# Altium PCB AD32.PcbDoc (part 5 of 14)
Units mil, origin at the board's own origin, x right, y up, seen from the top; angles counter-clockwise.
Board outline 7007.87 x 4368.85 mil, 12 copper layers (Top Layer, Int1 (GND), Int2 (AVDD), Int3 (DVDD), Int4 (GND), Int5 (ST), Int6 (SB), Int8 (AGND), Int7 (AVCC), Int9 (VCCA), Int10 (GND), Bottom Layer), stack 60.136 mil thick; 1350 components, 880 nets, 4712 pads, 2835 vias.
Unrouted connection lines stored in the file: 19.
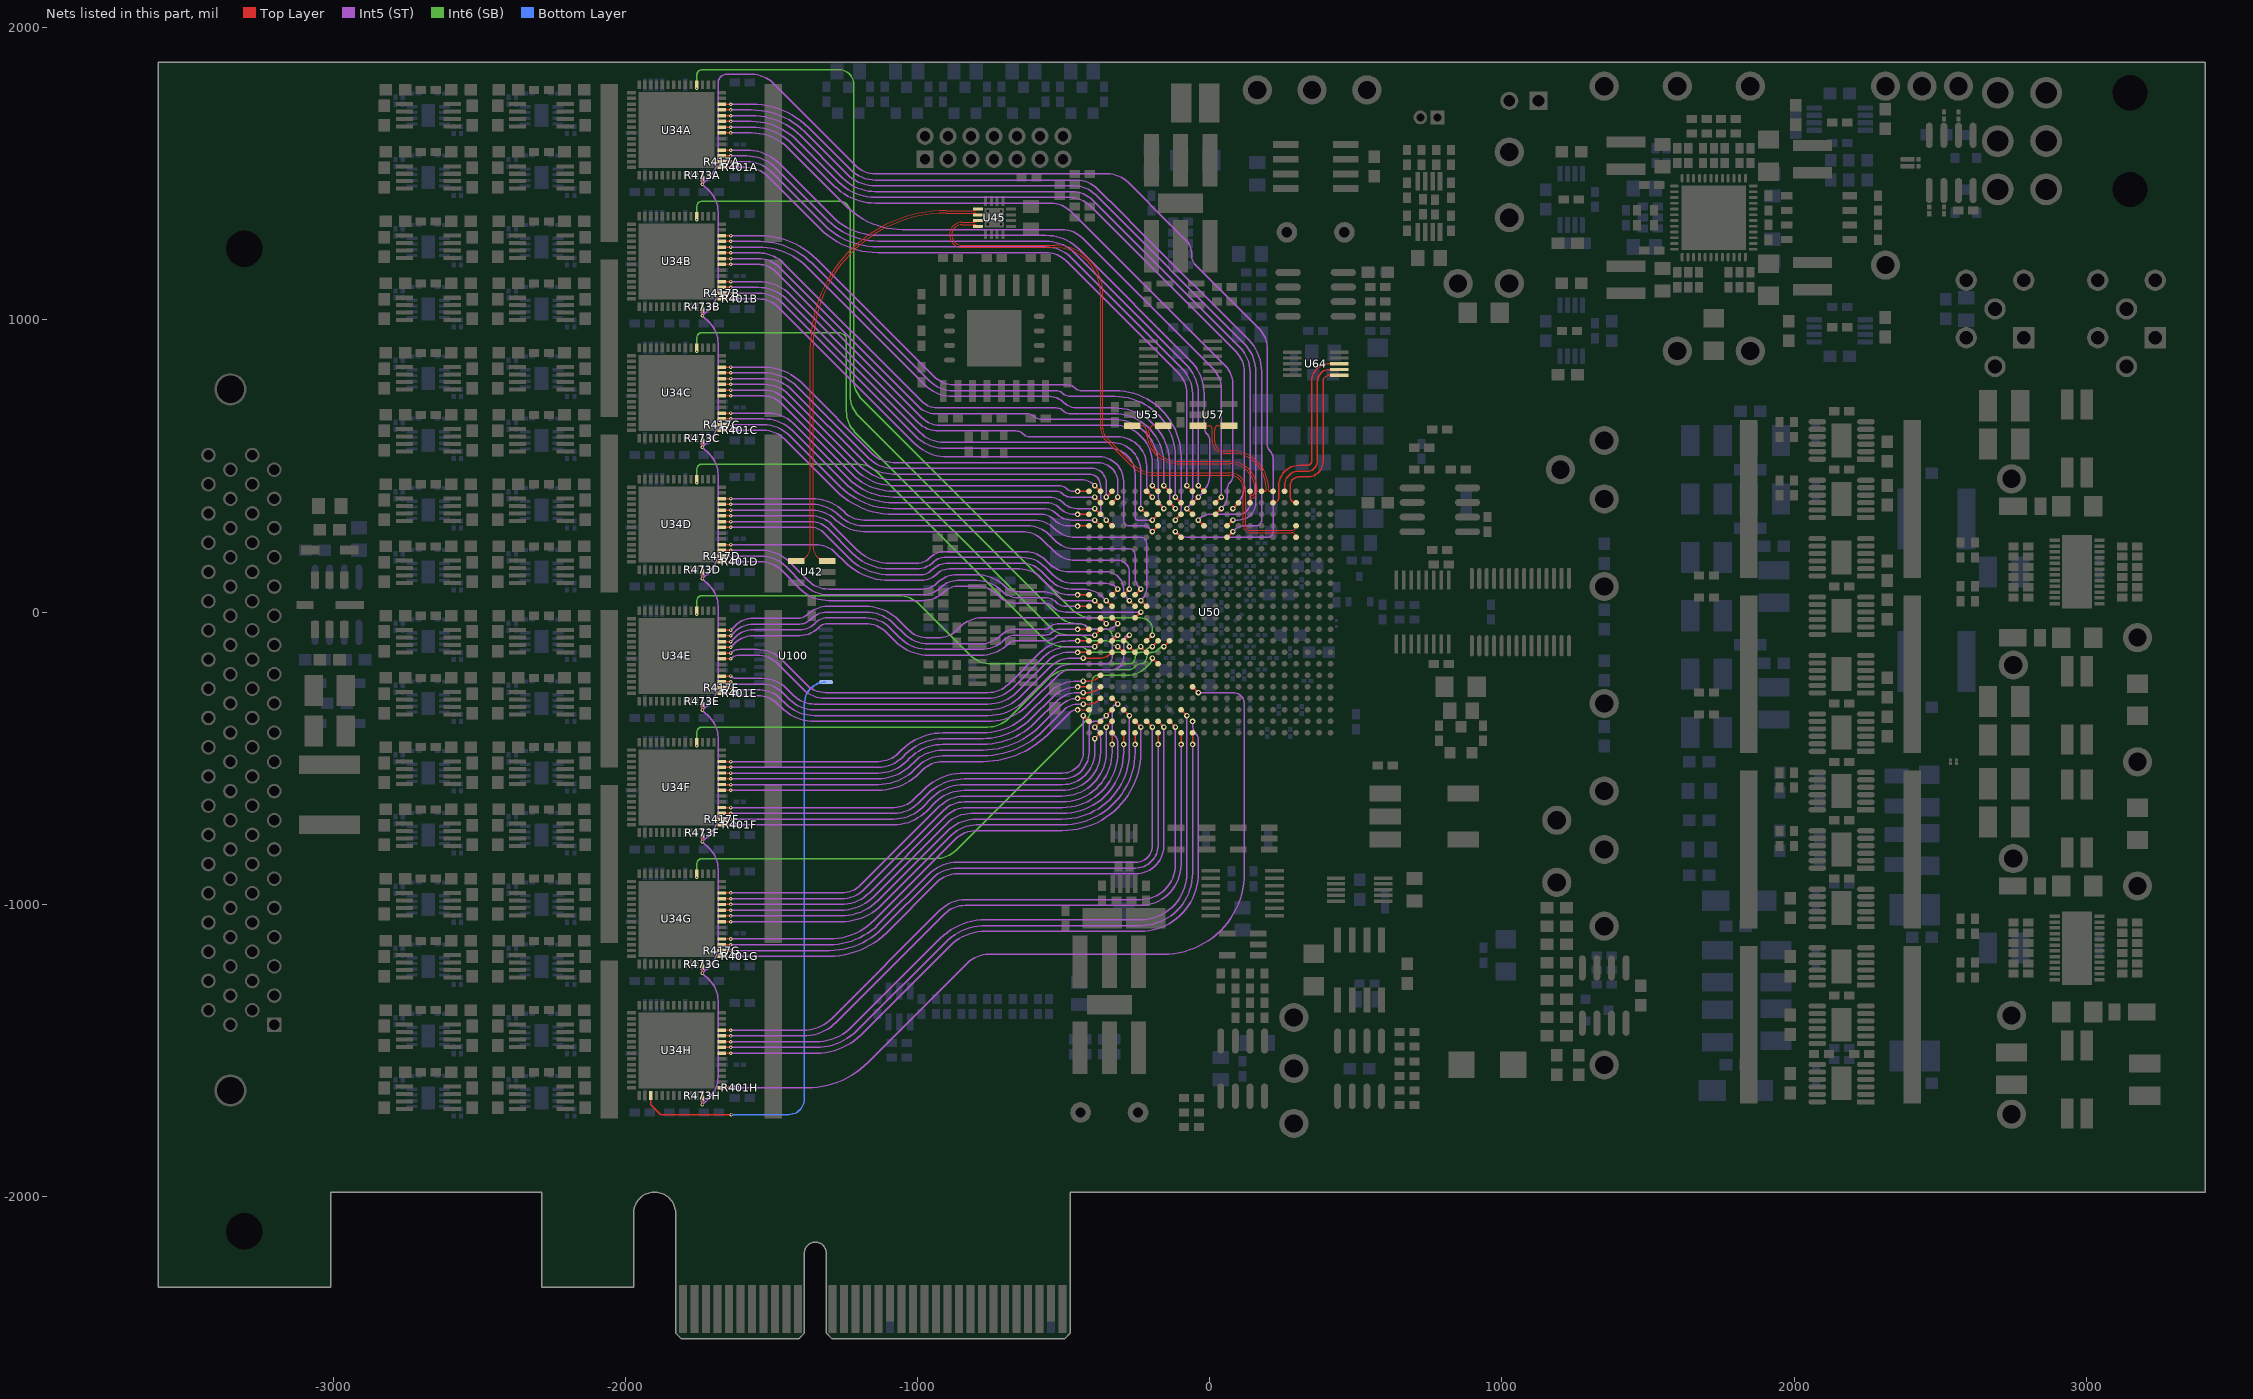
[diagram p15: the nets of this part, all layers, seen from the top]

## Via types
v1: diameter 12, hole 6, Top Layer to Bottom Layer, tented both sides, 1497 vias
v2: diameter 20, hole 10, Top Layer to Bottom Layer, tented both sides, 364 vias
v3: diameter 19, hole 10, Top Layer to Bottom Layer, tented both sides, 347 vias
v4: diameter 14, hole 7, Top Layer to Bottom Layer, tented both sides, 228 vias
v5: diameter 19.68, hole 7.87, Top Layer to Bottom Layer, 225 vias
v6: diameter 19.02, hole 10, Top Layer to Bottom Layer, tented both sides, 85 vias
v7: diameter 20, hole 10, Top Layer to Bottom Layer, 32 vias
v8: diameter 40, hole 20, Top Layer to Bottom Layer, tented both sides, 14 vias
v9: diameter 30, hole 15, Top Layer to Bottom Layer, tented both sides, 12 vias
v10: diameter 25, hole 13, Top Layer to Bottom Layer, 8 vias
v11: diameter 40, hole 20, Top Layer to Bottom Layer, 6 vias
v12: diameter 50, hole 20, Top Layer to Bottom Layer, 6 vias
v13: diameter 66, hole 47, Top Layer to Bottom Layer, tented both sides, 3 vias
v14: diameter 63, hole 45, Top Layer to Bottom Layer, 2 vias
v15: diameter 50, hole 25, Top Layer to Bottom Layer, 2 vias
v16: diameter 12, hole 6, Top Layer to Bottom Layer, 2 vias
v17: diameter 60, hole 40, Top Layer to Bottom Layer, tented both sides, 1 vias
v18: diameter 60, hole 40, Top Layer to Bottom Layer, 1 vias

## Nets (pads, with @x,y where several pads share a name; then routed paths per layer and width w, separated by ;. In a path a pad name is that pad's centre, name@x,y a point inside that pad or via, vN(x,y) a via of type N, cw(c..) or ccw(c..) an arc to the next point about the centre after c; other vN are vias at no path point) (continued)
ACLK8: U34H.45 U100.8 | length 2070.8
  Top Layer w5: U34H.45@-1913.58,-1654.62 -1913.58,-1686.42 -1880,-1720 v1(-1637.5,-1720)
  Bottom Layer w5: v1(-1637.5,-1720) -1442.36,-1720 ccw(c-1442.36,-1665.14) -1387.5,-1665.14 -1387.5,-313.29 cw(c-1313.78,-313.29) U100.8@-1313.78,-239.57
ACLK.ACLKF: U50.AA6 U64.8 | length 632.8
  Top Layer w5: U50.AA6@216.54,374.02 ccw(c216.54,393.7) 236.22,393.7 236.22,433.07 cw(c305.12,433.07) 305.12,501.97 334.65,501.97 ccw(c334.65,515.75) 348.43,515.75 348.43,788.98 cw(c409.45,788.98) 409.21,850 ; U64.8@443.21,850 409.45,850 ; 409.21,850 cw(c409.45,788.98) 409.45,850 ; 409.21,850 409.45,850
ACLK.ACNVF: U50.AA4 U64.6 | length 570.9
  Top Layer w5: U50.AA4@295.28,374.02 cw(c295.28,393.7) 275.59,393.7 275.59,433.07 cw(c305.12,433.07) 305.12,462.6 334.65,462.6 ccw(c334.65,515.75) 387.8,515.75 387.8,788.98 cw(c409.45,788.98) 409.21,810.63 ; U64.6@443.21,810.63 409.45,810.63 ; 409.21,810.63 cw(c409.45,788.98) 409.45,810.63 ; 409.21,810.63 409.45,810.63
ACLK.AINF: U50.AB5 U64.7 | length 551.2
  Top Layer w5: U50.AB5@255.91,413.39 255.91,433.07 cw(c305.12,433.07) 305.12,482.28 334.65,482.28 ccw(c334.65,515.75) 368.11,515.75 368.11,788.98 cw(c409.45,788.98) 409.21,830.31 ; U64.7@443.21,830.32 409.45,830.32 ; 409.21,830.31 cw(c409.45,788.98) 409.45,830.32 ; 409.21,830.32 409.45,830.32
ACLK.CNTROUTF_N: U50.AA8 U53.4 | length 606.2
  Top Layer w4: U53.4@-159.35,637.6 -190.98,637.6 ccw(c-190.98,620.08) -208.5,620.08 -208.5,615.87 ccw(c-108.5,615.87) -108.5,515.87 68.98,515.87 cw(c68.98,423.31) 161.54,423.31 161.54,411.48 cw(c139.76,411.48) 139.76,389.7 ccw(c139.76,387.73) 137.8,387.73 U50.AA8@137.8,374.02
ACLK.CNTROUTF_P: U50.AB8 U53.3 | length 593.6
  Top Layer w4: U53.3@-265.65,637.6 -234.02,637.6 cw(c-234.02,620.08) -216.5,620.08 -216.5,615.87 ccw(c-108.5,615.87) -108.5,507.87 68.98,507.87 cw(c68.98,423.31) 153.54,423.31 153.54,411.48 cw(c139.76,411.48) 139.76,397.7 cw(c139.76,399.67) 137.8,399.67 U50.AB8@137.8,413.39
ACLK.OSCCLKA_N: U42.3 U45.10 | length 1587.8
  Top Layer w4: U42.3@-1309.35,174.9 cw(c-1309.35,223.55) -1358,223.55 -1358,909.32 cw(c-902.14,909.32) -902.14,1365.19 -806.89,1365.19 cw(c-806.89,1346.94) U45.10@-794,1359.84
ACLK.OSCCLKA_P: U42.4 U45.9 | length 1602
  Top Layer w4: U42.4@-1415.65,174.9 ccw(c-1415.65,223.55) -1367,223.55 -1367,909.32 cw(c-902.14,909.32) -902.14,1374.19 -806.89,1374.19 ccw(c-806.89,1392.43) U45.9@-794,1379.53
ACLK.OSCCLKF_N: U45.11 U50.V4 | length 2134.8
  Top Layer w4: -891.21,1291.8 ccw(c-847.32,1291.8) -847.32,1247.91 -529.95,1247.91 cw(c-529.95,1091.97) -374.02,1091.97 -374.02,629.92 ccw(c-316.99,629.92) -357.31,589.6 -267.73,500.01 ccw(c-191.36,576.38) -191.36,468.38 68.9,468.38 cw(c68.9,423.1) 114.17,423.1 114.17,296.72 ccw(c139.3,296.72) 139.3,271.59 279.59,271.59 cw(c279.59,255.91) U50.V4@295.28,255.91
  Top Layer w4.02: -891.21,1291.8 cw(c-848.68,1291.8) -848.68,1334.33 -808.06,1334.33 ccw(c-808.06,1354.22) U45.11@-794,1340.16
ACLK.OSCCLKF_P: U45.12 U50.W4 | length 2109.7
  Top Layer w4: -883.21,1291.8 ccw(c-847.32,1291.8) -847.32,1255.91 -529.95,1255.91 cw(c-529.95,1091.97) -366.02,1091.97 -366.02,629.92 ccw(c-316.99,629.92) -351.66,595.25 -262.07,505.67 ccw(c-191.36,576.38) -191.36,476.38 68.9,476.38 cw(c68.9,423.1) 122.17,423.1 122.17,296.72 ccw(c139.3,296.72) 139.3,279.59 279.59,279.59 ccw(c279.59,295.28) U50.W4@295.28,295.28
  Top Layer w4.02: -883.21,1291.8 cw(c-848.71,1291.8) -848.71,1326.3 -808.06,1326.3 cw(c-808.06,1306.41) U45.12@-794,1320.47
ACLK.SYNCF_N: U50.AB6 U57.4 | length 398.2
  Top Layer w4: U57.4@65.65,637.6 28.11,637.6 ccw(c28.11,625.98) 16.5,625.98 16.5,583.89 ccw(c47.89,583.89) 47.89,552.5 71.82,552.5 cw(c71.82,423.3) 200.85,416.73 ccw(c204.19,416.73) 204.19,413.39 U50.AB6@216.54,413.39
ACLK.SYNCF_P: U50.AB7 U57.3 | length 398.2
  Top Layer w4: U57.3@-40.65,637.6 -3.11,637.6 cw(c-3.11,625.98) 8.5,625.98 8.5,583.89 ccw(c47.89,583.89) 47.89,544.5 71.83,544.5 cw(c71.83,423.3) 192.85,416.73 cw(c189.51,416.73) 189.51,413.39 U50.AB7@177.17,413.39
ADC1.CS: R401A.1 U34A.1 U50.AB13 | length 2273.3
  Top Layer w5: U34A.1@-1670.38,1522.05 v1(-1639.57,1522.05) ; v6(-78.74,433.07) U50.AB13@-59.05,413.39
  Int5 (ST) w5: v1(-1639.57,1522.05) -1585.12,1522.05 cw(c-1585.12,1422.05) -1514.41,1492.76 -1333.15,1311.49 ccw(c-1137.16,1507.48) -1137.16,1230.32 -561.11,1230.32 cw(c-561.11,1130.32) -490.4,1201.03 -108.03,818.66 cw(c-178.74,747.95) -78.74,747.95 v6(-78.74,433.07)
  Bottom Layer w5: v1(-1639.57,1522.05) R401A.1@-1620.69,1522.05
ADC1.D0: U34A.10 U50.W12 | length 2855.7
  Top Layer w5: U34A.10@-1670.38,1699.21 v1@-1639.5,1699.21 ; v6(-39.5,314.96) U50.W12@-19.68,295.28
  Int5 (ST) w5: v1(-1639.57,1699.21) -1568.81,1699.21 cw(c-1568.81,1461.42) -1400.67,1629.56 -1256.83,1485.73 ccw(c-1144.36,1598.2) -1144.36,1439.14 -471.68,1439.14 cw(c-471.68,1339.14) -400.97,1409.85 102.74,906.15 cw(c18.11,821.52) 137.8,821.52 137.8,373.56 cw(c98.88,373.56) 98.88,334.65 0,334.65 ccw(c0,287.12) -33.6,320.74 v6@-39.37,314.96
ADC1.D1: U34A.9 U50.AA9 | length 2649.5
  Top Layer w5: U34A.9@-1670.38,1679.53 v1(-1639.57,1679.53) ; v6(78.74,354.33) U50.AA9@98.43,374.02
  Int5 (ST) w5: v1(-1639.57,1679.53) -1568.81,1679.53 cw(c-1568.81,1461.42) -1414.59,1615.64 -1270.75,1471.81 ccw(c-1144.36,1598.2) -1144.36,1419.46 -479.83,1419.46 cw(c-479.83,1319.46) -409.12,1390.17 88.82,892.23 cw(c18.11,821.52) 118.11,821.52 118.11,435.12 cw(c18.11,435.12) 88.82,364.41 v6(78.74,354.33)
ADC1.D2: U34A.8 U50.Y11 | length 2574.8
  Top Layer w5: U34A.8@-1670.38,1659.84 v1(-1639.57,1659.84) ; U50.Y11@19.69,334.65 v6(39.37,354.33)
  Int5 (ST) w5: v1(-1639.57,1659.84) -1568.81,1659.84 cw(c-1568.81,1461.42) -1428.51,1601.72 -1284.67,1457.89 ccw(c-1144.36,1598.2) -1144.36,1399.77 -545.53,1399.77 cw(c-545.53,1299.77) -474.81,1370.48 52.29,843.38 cw(c-11.55,779.53) 78.74,779.53 78.74,466.68 cw(c45.14,466.68) 68.9,442.91 ccw(c92.66,419.15) 59.06,419.15 59.06,393.7 cw(c11.53,393.7) 45.13,360.1 v6(39.37,354.33)
ADC1.D3: U34A.7 U50.AA11 | length 2739.2
  Top Layer w5: U34A.7@-1670.38,1640.16 v1(-1639.57,1640.16) ; U50.AA11@19.69,374.02 v6(39.37,393.7)
  Int5 (ST) w5: v1(-1639.57,1640.16) -1568.81,1640.16 cw(c-1568.81,1461.42) -1442.43,1587.81 -1242.39,1387.77 -1242.35,1387.73 ccw(c-1052.74,1577.34) -1052.74,1309.2 ; -1052.71,1309.2 -506.13,1309.2 cw(c-506.13,1209.2) -435.42,1279.91 ; -243.01,1087.5 -435.42,1279.91 ; v6(39.37,393.7) 39.37,763.7 ccw(c-60.63,763.7) 10.08,834.41 -435.42,1279.91
ADC1.DCLK: U34A.11 U50.W10 | length 2793.6
  Top Layer w5: U34A.11@-1670.38,1718.9 v1(-1639.57,1718.9) ; U50.W10@59.06,295.28 v6(78.74,314.96)
  Int5 (ST) w5: v1(-1639.57,1718.9) -1568.81,1718.9 cw(c-1568.81,1461.42) -1386.75,1643.48 -1242.91,1499.65 ccw(c-1144.36,1598.2) -1144.36,1458.83 -463.52,1458.83 cw(c-463.52,1358.83) -392.81,1429.54 116.66,920.07 cw(c18.11,821.52) 157.48,821.52 157.48,374.5 cw(c97.95,374.5) 97.95,314.96 v6(78.74,314.96)
ADC1.GPIO7: U34A.18 U50.J17 | length 3076.4
  Top Layer w5: U50.J17@-216.54,-98.43 v6(-196.85,-78.74)
  Int6 (SB) w5: v1(-1756.1,1792.69) -1756.1,1837.65 cw(c-1737.5,1837.65) -1737.5,1856.25 -1268.75,1856.25 cw(c-1268.75,1806.25) -1218.75,1806.25 -1218.75,797.57 ccw(c-1118.75,797.57) -1189.46,726.86 -472.14,9.54 ; -472.2,9.6 ccw(c-401.49,80.32) -472.14,9.54 ; -236.11,-19.73 -236.16,-19.69 ; v6(-196.85,-78.74) -196.85,-59.06 ccw(c-236.22,-59.06) -236.16,-19.69 ; -472.14,9.54 ccw(c-401.49,80.32) -401.49,-19.68 -236.22,-19.68 ; -236.22,-19.68 cw(c-236.22,-59.06) -236.16,-19.69 ; -236.22,-19.68 -236.16,-19.68
ADC1.ODR: U34A.12 U50.V10 | length 2888.4
  Top Layer w5: U34A.12@-1670.38,1738.58 v1(-1639.57,1738.58) ; U50.V10@59.06,255.91 v6(78.74,275.59)
  Int5 (ST) w5: v1(-1639.57,1738.58) -1568.81,1738.58 cw(c-1568.81,1461.42) -1372.83,1657.4 -1228.99,1513.57 ccw(c-1144.36,1598.2) -1144.36,1478.51 -455.5,1478.51 cw(c-455.5,1378.51) -384.78,1449.22 -303.62,1368.06 ; -303.66,1368.1 -303.62,1368.06 ; v6(78.74,275.59) 84.52,281.37 cw(c118.11,247.75) 118.11,295.28 157.92,295.28 ccw(c157.92,314.52) 177.17,314.52 177.17,824.32 ccw(c25.17,824.32) 132.62,931.82 -246.06,1310.5 -303.62,1368.06
ADC1.RST: R473A.1 R473B.1 R473C.1 R473D.1 R473E.1 R473F.1 R473G.1 R473H.1 U34A.54 U34B.54 U34C.54 U34D.54 U34E.54 U34F.54 U34G.54 U34H.54 U50.V14 | length 7492.9
  Top Layer w5: v1(-1736.42,-1685.43) U34H.54@-1736.42,-1654.62 ; v1(-1736.42,-1235.43) U34G.54@-1736.42,-1204.62 ; v1(-1736.42,-785.43) U34F.54@-1736.42,-754.62 ; v1(-1736.42,-335.43) U34E.54@-1736.42,-304.62 ; v1(-1736.42,114.57) U34D.54@-1736.42,145.38 ; v1(-1736.42,564.57) U34C.54@-1736.42,595.38 ; v1(-1736.42,1014.57) U34B.54@-1736.42,1045.38 ; v1(-1736.42,1464.57) U34A.54@-1736.42,1495.38 ; v3(-118.11,275.59) U50.V14@-98.43,255.91
  Int5 (ST) w5: v1(-1736.42,-1685.43) -1712.36,-1661.38 ccw(c-1783.07,-1590.66) -1683.07,-1590.66 -1683.07,-1330.2 ccw(c-1783.07,-1330.2) -1712.36,-1259.49 v1(-1736.42,-1235.43) -1712.36,-1211.38 ccw(c-1783.07,-1140.66) -1683.07,-1140.66 -1683.07,-880.2 ccw(c-1783.07,-880.2) -1712.36,-809.49 v1(-1736.42,-785.43) -1712.36,-761.38 ccw(c-1783.07,-690.66) -1683.07,-690.66 -1683.07,-430.2 ccw(c-1783.07,-430.2) -1712.36,-359.49 v1(-1736.42,-335.43) -1712.36,-311.38 ccw(c-1783.07,-240.66) -1683.07,-240.66 -1683.07,19.8 ccw(c-1783.07,19.8) -1712.36,90.51 v1(-1736.42,114.57) -1712.36,138.62 ccw(c-1783.07,209.34) -1683.07,209.34 -1683.07,469.8 ccw(c-1783.07,469.8) -1712.36,540.51 v1(-1736.42,564.57) -1712.36,588.62 ccw(c-1783.07,659.34) -1683.07,659.34 -1683.07,919.8 ccw(c-1783.07,919.8) -1712.36,990.51 v1(-1736.42,1014.57) -1712.36,1038.62 ccw(c-1783.07,1109.34) -1683.07,1109.34 -1683.07,1369.8 ccw(c-1783.07,1369.8) -1712.36,1440.51 v1(-1736.42,1464.57) -1712.36,1488.62 ccw(c-1783.07,1559.34) -1683.07,1559.34 -1683.07,1811.02 cw(c-1653.54,1811.02) -1653.54,1840.55 -1567.01,1840.55 cw(c-1567.01,1740.55) -1496.3,1811.26 -1214.33,1529.29 ccw(c-1143.62,1600) -1143.62,1500 -350.48,1500 cw(c-350.48,1400) -279.77,1470.71 -135.44,1326.38 -135.39,1326.34 -90.31,1281.25 -78.84,1269.78 ; v3(-118.11,275.59) ccw(c-70.59,323.11) -70.59,255.91 197.62,255.91 ccw(c197.62,274.82) 216.54,274.82 216.54,526.35 ccw(c181.42,526.35) 206.25,551.18 cw(c228.94,573.87) 196.85,573.87 196.85,900.4 ccw(c96.85,900.4) 167.56,971.11 -48.36,1187.03 -48.46,1187.13 cw(c-14.36,1221.11) -62.5,1221.11 ; -76.48,1267.42 -78.84,1269.78 ; -62.5,1221.14 -62.5,1230.32 ccw(c-118.34,1230.32) -78.84,1269.78
  Bottom Layer w5: v1(-1736.42,-1685.43) R473H.1@-1736.42,-1666.56 ; v1(-1736.42,-1235.43) R473G.1@-1736.42,-1216.56 ; v1(-1736.42,-785.43) R473F.1@-1736.42,-766.56 ; v1(-1736.42,-335.43) R473E.1@-1736.42,-316.56 ; v1(-1736.42,114.57) R473D.1@-1736.42,133.44 ; v1(-1736.42,564.57) R473C.1@-1736.42,583.44 ; v1(-1736.42,1014.57) R473B.1@-1736.42,1033.44 ; v1(-1736.42,1464.57) R473A.1@-1736.42,1483.44
ADC1.SCLK: R417A.1 U34A.2 U50.Y13 | length 2389.1
  Top Layer w5: U34A.2@-1670.38,1541.73 v1(-1639.57,1541.73) ; v6(-78.74,354.33) U50.Y13@-59.05,334.65
  Int5 (ST) w5: v1(-1639.57,1541.73) -1585.12,1541.73 cw(c-1585.12,1422.05) -1500.49,1506.68 -1319.23,1325.41 ccw(c-1137.16,1507.48) -1137.16,1250 -561.11,1250 cw(c-561.11,1130.32) -476.48,1214.95 -94.11,832.58 cw(c-178.74,747.95) -59.05,747.95 -59.05,393.7 cw(c-106.58,393.7) -72.97,360.11 v6(-78.74,354.33)
  Bottom Layer w5: R417A.1@-1658.44,1541.73 v1(-1639.57,1541.73)
ADC1.SI: U34A.4 U50.AA13 | length 2403.9
  Top Layer w5: U34A.4@-1670.38,1581.1 v1@-1639.53,1581.1 ; U50.AA13@-59.05,374.02 v6(-39.37,393.7)
  Int5 (ST) w5: v1(-1639.57,1581.1) -1585.12,1581.1 cw(c-1585.12,1422.05) -1472.65,1534.52 -1291.39,1353.25 ccw(c-1137.16,1507.48) -1137.16,1289.37 -561.11,1289.37 cw(c-561.11,1130.32) -448.64,1242.78 -66.27,860.42 cw(c-178.74,747.95) -19.68,747.95 -19.68,634 ccw(c13.92,634) -9.84,610.24 cw(c-33.6,586.47) 0,586.47 0,474.49 cw(c-100,474.49) -29.29,403.78 v6(-39.37,393.7)
ADC1.SO: U34A.3 U50.AB12 | length 2316.3
  Top Layer w5: U34A.3@-1670.38,1561.42 v1(-1639.57,1561.42) ; v6(-39.37,433.07) U50.AB12@-19.68,413.39
  Int5 (ST) w5: v1(-1639.57,1561.42) -1585.12,1561.42 cw(c-1585.12,1422.05) -1486.57,1520.6 -1305.31,1339.33 ccw(c-1137.16,1507.48) -1137.16,1269.69 -561.11,1269.69 cw(c-561.11,1130.32) -462.56,1228.86 -80.19,846.5 cw(c-178.74,747.95) -39.37,747.95 v6(-39.37,433.07)
ADC2.CS: R401B.1 U34B.1 U50.W16 | length 1933.4
  Top Layer w5: U34B.1@-1670.38,1072.05 v1(-1639.57,1072.05) ; v3(-196.85,275.59) U50.W16@-177.17,295.28
  Int5 (ST) w5: v1(-1639.57,1072.05) -1545.76,1072.05 cw(c-1545.76,973.92) -1476.38,1043.31 -1011.15,578.08 ccw(c-898.68,690.55) -898.68,531.5 -378.24,531.5 cw(c-378.24,448.53) -295.28,448.53 -295.28,314.96 ccw(c-275.59,314.96) -275.59,295.28 -216.54,295.28 v3(-196.85,275.59)
  Bottom Layer w5: v1(-1639.57,1072.05) R401B.1@-1620.69,1072.05
ADC2.D0: U34B.10 U50.AA15 | length 2042.5
  Top Layer w5: U34B.10@-1670.38,1249.21 v1@-1639.5,1249.21 ; U50.AA15@-137.8,374.02 v6(-118.11,354.33)
  Int5 (ST) w5: v1(-1639.57,1249.21) -1545.15,1249.21 ; -1538.75,1249.21 -1545.15,1249.21 ; v6(-118.11,354.33) -123.88,360.1 cw(c-90.27,393.7) -137.8,393.7 -137.8,509.71 ccw(c-326.91,509.71) -326.91,698.82 -454.44,698.82 cw(c-454.44,766.03) -501.97,718.5 ccw(c-549.49,670.98) -549.49,738.19 -879.95,738.19 cw(c-879.95,872.61) -975,777.56 -1377,1179.56 ccw(c-1545.15,1011.42) -1545.15,1249.21
ADC2.D1: U34B.9 U50.AB15 | length 1936.4
  Top Layer w5: U34B.9@-1670.38,1229.53 v1(-1639.57,1229.53) ; v6(-157.48,433.07) U50.AB15@-137.8,413.39
  Int5 (ST) w5: v1(-1639.57,1229.53) -1545.76,1229.53 ; -1538.75,1229.53 -1545.76,1229.53 ; v6(-157.48,433.07) -157.48,507.4 ccw(c-329.21,507.4) -329.21,679.13 -478.21,679.13 cw(c-478.21,712.74) -501.97,688.98 ccw(c-525.73,665.21) -525.73,698.82 -930.31,698.82 cw(c-930.31,778.59) -986.69,722.16 -1457.51,1192.97 ccw(c-1545.76,1104.72) -1545.76,1229.53
ADC2.D2: U34B.8 U50.AA16 | length 1991.6
  Top Layer w5: U34B.8@-1670.38,1209.84 v1(-1639.57,1209.84) ; U50.AA16@-177.17,374.02 v6(-157.48,354.33)
  Int5 (ST) w5: v1(-1639.57,1209.84) -1545.76,1209.84 ; -1538.75,1209.84 -1545.76,1209.84 ; v6(-157.48,354.33) cw(c-109.96,401.85) -177.17,401.85 -177.17,510.16 ccw(c-326.45,510.16) -326.45,659.45 -576.63,659.45 cw(c-576.63,693.05) -600.39,669.29 ccw(c-624.16,645.53) -624.16,679.13 -939.29,679.13 cw(c-939.29,759.16) -995.85,702.55 -1473.02,1179.71 ccw(c-1545.76,1106.97) -1545.76,1209.84
ADC2.D3: U34B.7 U50.AB16 | length 1879.7
  Top Layer w5: U34B.7@-1670.38,1190.16 v1(-1639.57,1190.16) ; v3(-196.85,433.07) U50.AB16@-177.17,413.39
  Int5 (ST) w5: v1(-1639.57,1190.16) -1545.76,1190.16 ; -1538.75,1190.16 -1545.76,1190.16 ; v3(-196.85,433.07) -196.85,509.58 ccw(c-327.04,509.58) -327.04,639.76 -923.15,639.76 cw(c-923.15,729.35) -986.49,666 -1485.82,1165.34 ccw(c-1545.76,1105.38) -1545.76,1190.16
ADC2.DCLK: U34B.11 U50.AA14 | length 2041.4
  Top Layer w5: U34B.11@-1670.38,1268.9 v1(-1639.57,1268.9) ; v6(-118.11,393.7) U50.AA14@-98.43,374.02
  Int5 (ST) w5: v1(-1639.57,1268.9) -1543.46,1268.9 ; -1538.75,1268.9 -1543.46,1268.9 ; v6(-118.11,393.7) -118.11,531.5 ccw(c-324.8,531.5) -324.8,738.19 -478.21,738.19 cw(c-478.21,771.79) -501.97,748.03 ccw(c-525.73,724.27) -525.73,757.87 -877.07,757.87 cw(c-877.07,875.49) -960.23,792.31 -1361.4,1193.48 ccw(c-1543.46,1011.42) -1543.46,1268.9
ADC2.GPIO7: U34B.18 U50.H18 | length 2678.4
  Top Layer w5: v6(-275.59,-118.11) U50.H18@-255.91,-137.8
  Int6 (SB) w5: v1(-1756.1,1342.69) -1756.1,1387.65 cw(c-1737.5,1387.65) -1737.5,1406.25 -1268.75,1406.25 cw(c-1268.75,1368.75) -1231.25,1368.75 -1231.25,741.18 ccw(c-1131.25,741.18) -1201.96,670.46 -578.74,47.24 ; -517.18,-14.32 -578.74,47.24 ; -334.65,-78.74 ccw(c-354.33,-78.74) -354.33,-59.06 -399.47,-59.06 cw(c-399.47,-25.45) -423.23,-49.21 ccw(c-446.99,-72.97) -446.99,-39.37 -456.69,-39.37 cw(c-456.69,46.17) -517.15,-14.34 -578.74,47.24 ; -334.52,-78.87 ccw(c-314.96,-78.87) -314.96,-98.43 -295.28,-98.43 cw(c-295.28,-118.11) v6(-275.59,-118.11)
ADC2.ODR: U34B.12 U50.Y14 | length 2156.1
  Top Layer w5: U34B.12@-1670.38,1288.58 v1(-1639.57,1288.58) ; v6(-118.11,314.96) U50.Y14@-98.43,334.65
  Int5 (ST) w5: v1(-1639.57,1288.58) -1541.77,1288.58 ; -1538.75,1288.58 -1541.77,1288.58 ; v6@-118.63,314.44 v6(-118.11,314.96) -112.35,320.73 ccw(c-145.95,354.33) -98.43,354.33 -98.43,531.5 ccw(c-324.8,531.5) -324.8,757.87 -438.84,757.87 cw(c-438.84,791.48) -462.6,767.72 ccw(c-486.36,743.95) -486.36,777.56 -874.52,777.56 cw(c-874.52,877.56) -945.23,806.85 -1345.79,1207.4 ccw(c-1541.77,1011.42) -1541.77,1288.58
ADC2.SCLK: R417B.1 U34B.2 U50.Y16 | length 1932.8
  Top Layer w5: U34B.2@-1670.38,1091.73 v1(-1639.57,1091.73) ; v3(-196.85,314.96) U50.Y16@-177.17,334.65
  Int5 (ST) w5: v1(-1639.57,1091.73) -1545.76,1091.73 cw(c-1545.76,973.92) -1462.46,1057.23 -1007.08,601.84 ccw(c-908.53,700.39) -908.53,561.02 -344.49,561.02 cw(c-344.49,472.44) -255.91,472.44 -255.91,324.8 ccw(c-246.06,324.8) -246.06,314.96 v3(-196.85,314.96)
  Bottom Layer w5: R417B.1@-1658.44,1091.73 v1(-1639.57,1091.73)
ADC2.SI: U34B.4 U50.AB17 | length 1856.2
  Top Layer w5: U34B.4@-1670.38,1131.1 v1@-1639.53,1131.1 ; U50.AB17@-216.54,413.39 v3(-196.85,393.7)
  Int5 (ST) w5: v1(-1639.57,1131.1) -1545.76,1131.1 cw(c-1545.76,973.92) -1434.62,1085.07 -998.92,649.37 ccw(c-928.21,720.08) -928.21,620.08 -663.53,620.08 cw(c-663.53,586.47) -639.76,610.24 ccw(c-616,634) -616,600.39 -316.54,600.39 cw(c-316.54,500.39) -216.54,500.39 ; -216.54,500 -216.54,441.22 ccw(c-149.33,441.22) v3(-196.85,393.7)
ADC2.SO: U34B.3 U50.Y17 | length 1854.2
  Top Layer w5: U34B.3@-1670.38,1111.42 v1(-1639.57,1111.42) ; v3(-236.22,354.33) U50.Y17@-216.54,334.65
  Int5 (ST) w5: v1(-1639.57,1111.42) -1545.76,1111.42 cw(c-1545.76,973.92) -1448.54,1071.15 -993.16,615.76 ccw(c-908.53,700.39) -908.53,580.71 -336.22,580.71 cw(c-336.22,480.71) -236.22,480.71 v3(-236.22,354.33)
ADC3.CS: R401C.1 U34C.1 U50.W22 | length 1389.1
  Top Layer w5: U34C.1@-1670.38,622.05 v1(-1639.57,622.05) ; v3(-452.76,295.28) U50.W22@-413.39,295.28
  Int5 (ST) w5: v1(-1639.57,622.05) -1527.56,622.05 cw(c-1527.56,520.3) -1455.61,592.24 -1279.19,415.83 ccw(c-1083.21,611.81) -1083.21,334.65 -579.02,334.65 cw(c-579.02,267.44) -531.5,314.96 ccw(c-483.97,362.48) -483.97,295.28 v3(-452.76,295.28)
  Bottom Layer w5: v1(-1639.57,622.05) R401C.1@-1620.69,622.05
ADC3.D0: U34C.10 U50.W20 | length 1594.3
  Top Layer w5: U34C.10@-1670.38,799.21 v1@-1639.5,799.21 ; v3(-354.33,314.96) U50.W20@-334.65,295.28
  Int5 (ST) w5: v1(-1639.57,799.21) -1525.43,799.21 cw(c-1525.43,659.84) -1426.89,758.39 -1181.75,513.26 ccw(c-1083.21,611.81) -1083.21,472.44 -413.47,472.44 cw(c-413.47,432.99) -374.02,432.99 -374.02,354.33 ccw(c-326.49,354.33) -360.1,320.73 v3(-354.33,314.96)
ADC3.D1: U34C.9 U50.AB21 | length 1433.1
  Top Layer w5: U34C.9@-1670.38,779.53 v1(-1639.57,779.53) ; v3(-393.7,433.07) U50.AB21@-374.02,413.39
  Int5 (ST) w5: v1(-1639.57,779.53) -1525.43,779.53 cw(c-1525.43,659.84) -1440.8,744.47 -1195.67,499.34 ccw(c-1083.21,611.81) -1083.21,452.76 -441.22,452.76 cw(c-441.22,385.55) v3(-393.7,433.07)
ADC3.D2: U34C.8 U50.AB22 | length 1385.2
  Top Layer w5: U34C.8@-1670.38,759.84 v1(-1639.57,759.84) ; v3(-452.76,413.39) U50.AB22@-413.39,413.39
  Int5 (ST) w5: v1(-1639.57,759.84) -1525.44,759.84 cw(c-1525.44,659.84) -1454.72,730.55 -1209.59,485.42 ccw(c-1083.21,611.81) -1083.21,433.07 -551.59,433.07 ; -551.18,433.07 -515.89,433.07 cw(c-515.89,399.47) -492.13,423.23 ccw(c-468.36,446.99) -468.36,413.39 v3(-452.76,413.39)
ADC3.D3: U34C.7 U50.AA21 | length 1432.5
  Top Layer w5: U34C.7@-1670.38,740.16 v1(-1639.57,740.16) ; v3(-393.7,393.7) U50.AA21@-374.02,374.02
  Int5 (ST) w5: v1(-1639.57,740.16) -1527.56,740.16 cw(c-1527.56,654.71) -1467.14,715.13 -1223.51,471.5 ccw(c-1083.21,611.81) -1083.21,413.39 -551.59,413.39 ; -551.18,413.39 -525.73,413.39 cw(c-525.73,379.78) -501.97,403.54 ccw(c-478.21,427.31) -478.21,393.7 v3(-393.7,393.7)
ADC3.DCLK: U34C.11 U50.AB20 | length 1544.1
  Top Layer w5: U34C.11@-1670.38,818.9 v1(-1639.57,818.9) ; v3(-354.33,393.7) U50.AB20@-334.65,413.39
  Int5 (ST) w5: v1(-1639.57,818.9) -1525.43,818.9 cw(c-1525.43,659.84) -1412.97,772.31 -1167.84,527.18 ccw(c-1083.21,611.81) -1083.21,492.13 -404.67,492.13 cw(c-404.67,441.79) -354.33,441.79 v3(-354.33,393.7)
ADC3.GPIO7: U34C.18 U50.H19 | length 2127.4
  Top Layer w5: v6(-314.96,-118.11) U50.H19@-295.28,-137.8
  Int6 (SB) w5: v1(-1756.1,892.69) -1756.1,937.65 cw(c-1737.5,937.65) -1737.5,956.25 -1268.75,956.25 cw(c-1268.75,931.25) -1243.75,931.25 -1243.75,686.75 ccw(c-1143.75,686.75) -1214.46,616.04 -546.13,-52.29 ccw(c-482.28,11.56) -482.28,-78.74 -446.99,-78.74 cw(c-446.99,-112.34) -423.23,-88.58 ccw(c-399.47,-64.82) -399.47,-98.43 -358.41,-98.43 cw(c-358.41,-132.03) -334.65,-108.27 -331.76,-111.15 ccw(c-314.96,-94.35) v6(-314.96,-118.11)
ADC3.ODR: U34C.12 U50.AA20 | length 1595.4
  Top Layer w5: U34C.12@-1670.38,838.58 v1(-1639.57,838.58) ; U50.AA20@-334.65,374.02 v3(-314.96,393.7)
  Int5 (ST) w5: v1(-1639.57,838.58) -1525.43,838.58 cw(c-1525.43,659.84) -1399.05,786.23 -1153.92,541.1 ccw(c-1083.21,611.81) -1083.21,511.81 -383.34,511.81 cw(c-383.34,443.43) -314.96,443.43 v3(-314.96,393.7)
ADC3.SCLK: R417C.1 U34C.2 U50.W21 | length 1436.7
  Top Layer w5: U34C.2@-1670.38,641.73 v1(-1639.57,641.73) ; v3(-393.7,314.96) U50.W21@-374.02,295.28
  Int5 (ST) w5: v1(-1639.57,641.73) -1527.56,641.73 cw(c-1527.56,520.3) -1441.69,606.16 -1265.27,429.74 ccw(c-1083.21,611.81) -1083.21,354.33 -569.18,354.33 cw(c-569.18,287.12) -521.65,334.65 ccw(c-474.13,382.17) -474.13,314.96 v3(-393.7,314.96)
  Bottom Layer w5: R417C.1@-1658.44,641.73 v1(-1639.57,641.73)
ADC3.SI: U34C.4 U50.Y21 | length 1419.6
  Top Layer w5: U34C.4@-1670.38,681.1 v1@-1639.53,681.1 ; v3(-393.7,354.33) U50.Y21@-374.02,334.65
  Int5 (ST) w5: v1(-1639.57,681.1) -1510.53,681.1 cw(c-1510.53,561.42) -1425.9,646.05 -1237.43,457.58 ccw(c-1083.21,611.81) -1083.21,393.7 -549.49,393.7 cw(c-549.49,326.49) -501.97,374.02 ccw(c-454.44,421.54) -454.44,354.33 v3(-393.7,354.33)
ADC3.SO: U34C.3 U50.Y22 | length 1370.3
  Top Layer w5: U34C.3@-1670.38,661.42 v1(-1639.57,661.42) ; v3(-452.76,334.65) U50.Y22@-413.39,334.65
  Int5 (ST) w5: v1(-1639.57,661.42) -1526.83,661.42 cw(c-1526.83,522.05) -1428.28,620.6 -1251.35,443.66 ccw(c-1083.21,611.81) -1083.21,374.02 -559.34,374.02 cw(c-559.34,306.81) -511.81,354.33 ccw(c-464.29,401.85) -464.29,334.65 v3(-452.76,334.65)
ADC4.CS: R401D.1 U34D.1 U50.L18 | length 1562.4
  Top Layer w5: U34D.1@-1670.38,172.05 v1(-1639.57,172.05) ; U50.L18@-255.91,-19.68 v6(-236.22,0)
  Int5 (ST) w5: v1(-1639.57,172.05) -1536.3,172.05 cw(c-1536.3,72.05) -1465.59,142.76 -1403.03,80.19 ccw(c-1304.48,178.74) -1304.48,39.37 -982.56,39.37 ccw(c-982.56,145.95) -907.2,70.59 cw(c-863.75,27.14) -863.75,88.58 -797.89,88.58 cw(c-797.89,-11.42) -727.18,59.29 -726.66,58.78 ccw(c-656.05,129.39) -656.05,29.53 -564.09,29.53 cw(c-564.09,-5.03) -539.65,19.41 ccw(c-492.8,66.25) -492.8,0 v6(-236.22,0)
  Bottom Layer w5: v1(-1639.57,172.05) R401D.1@-1620.69,172.05
ADC4.D0: U34D.10 U50.N19 | length 1556.1
  Top Layer w5: U34D.10@-1670.38,349.21 v1@-1639.5,349.21 ; U50.N19@-295.28,59.06 v3(-275.59,78.74)
  Int5 (ST) w5: v1(-1639.57,349.21) -1362.22,349.21 cw(c-1362.22,232.27) -1279.53,314.96 ccw(c-1184.48,410.01) -1184.48,275.59 -641.82,275.59 cw(c-641.82,175.59) -571.1,246.3 -531.26,206.45 ccw(c-460.55,277.17) -460.55,177.17 -314.96,177.17 cw(c-314.96,137.8) -275.59,137.8 v3(-275.59,78.74)
ADC4.D1: U34D.9 U50.M18 | length 1572.8
  Top Layer w5: U34D.9@-1670.38,329.53 v1(-1639.57,329.53) ; v3(-275.59,39.37) U50.M18@-255.91,19.69
  Int5 (ST) w5: v1(-1639.57,329.53) -1365.32,329.53 cw(c-1365.32,229.17) -1294.36,300.13 ; -1297.31,303.08 -1208.13,213.91 ccw(c-1095.66,326.38) -1095.66,167.32 -1004.69,167.32 ccw(c-1004.69,235.01) -956.83,187.15 cw(c-909.65,139.96) -909.65,206.69 -631.97,206.69 cw(c-631.97,106.69) -561.26,177.4 -550.94,167.08 ccw(c-480.23,237.8) -480.23,137.8 -354.33,137.8 cw(c-354.33,78.74) -295.28,78.74 ccw(c-247.75,78.74) -281.36,45.14 v3(-275.59,39.37)
ADC4.D2: U34D.8 U50.N20 | length 1487.6
  Top Layer w5: U34D.8@-1670.38,309.84 v1(-1639.57,309.84) ; U50.N20@-334.65,59.06 v3(-314.96,78.74)
  Int5 (ST) w5: v1(-1639.57,309.84) -1365.32,309.84 cw(c-1365.32,229.17) -1308.31,286.25 ; -1311.23,289.17 -1308.31,286.25 ; -1308.28,286.21 ccw(c-1365.32,229.17) -1308.31,286.25 ; v3(-314.96,78.74) -320.73,84.51 ccw(c-354.33,50.9) -354.33,98.43 -466.17,98.43 cw(c-466.17,198.43) -536.88,127.71 -562.85,153.68 ccw(c-643.3,73.23) -643.3,187.01 -909.65,187.01 ccw(c-909.65,139.96) -942.91,173.23 cw(c-1004.69,235.01) -1004.69,147.64 -1095.66,147.64 cw(c-1095.66,326.38) -1222.05,199.99 -1308.31,286.25
ADC4.D3: U34D.7 U50.M20 | length 1451.2
  Top Layer w5: U34D.7@-1670.38,290.16 v1(-1639.57,290.16) ; v3(-354.33,39.37) U50.M20@-334.65,19.69
  Int5 (ST) w5: v1(-1639.57,290.16) -1364.24,290.16 cw(c-1364.24,231.77) -1322.96,273.06 -1235.97,186.07 ccw(c-1095.66,326.38) -1095.66,127.95 -987.32,127.95 ccw(c-987.32,172.57) -955.77,141.02 cw(c-889.88,75.13) -925.54,161.22 cw(c-894.86,87.15) -894.86,167.32 -643.3,167.32 cw(c-643.3,73.23) -576.77,139.76 -545.04,108.03 ccw(c-474.33,178.74) -474.33,78.74 -433.07,78.74 cw(c-433.07,-16.31) -365.86,50.9 v3(-354.33,39.37)
ADC4.DCLK: U34D.11 U50.N18 | length 1621.5
  Top Layer w5: U34D.11@-1670.38,368.9 v1(-1639.57,368.9) ; U50.N18@-255.91,59.06 v3(-236.22,78.74)
  Int5 (ST) w5: v1(-1639.57,368.9) -1362.22,368.9 cw(c-1362.22,232.27) -1265.61,328.88 ccw(c-1184.48,410.01) -1184.48,295.28 -622.13,295.28 cw(c-622.13,195.28) -551.42,265.99 -531.26,245.82 ccw(c-460.55,316.54) -460.55,216.54 -275.59,216.54 cw(c-275.59,196.85) -255.91,196.85 -255.91,118.11 ccw(c-208.38,118.11) -241.99,84.5 v3(-236.22,78.74)
ADC4.GPIO7: U34D.18 U50.H17 | length 1864
  Top Layer w5: v6(-236.24,-118.42) -236.08,-118.42 -216.7,-137.8 U50.H17@-216.54,-137.8
  Int6 (SB) w5: v1(-1756.1,442.69) -1756.1,487.65 cw(c-1737.5,487.65) -1737.5,506.25 -1207.12,506.25 cw(c-1207.12,406.25) -1136.41,476.96 -570.56,-88.88 ; -570.63,-88.82 ccw(c-499.92,-18.11) -570.56,-88.88 ; -500,-118.11 -499.92,-118.11 ; -446.85,-118.11 -446.99,-118.11 ; v6@-236.22,-118.11 cw(c-283.74,-70.59) -283.74,-137.8 -399.47,-137.8 cw(c-399.47,-104.19) -423.23,-127.95 ccw(c-446.99,-151.71) -446.99,-118.11 ; -570.56,-88.88 ccw(c-499.92,-18.11) -499.92,-118.11 ; -499.92,-118.11 -446.99,-118.11
ADC4.ODR: U34D.12 U50.M17 | length 1731.2
  Top Layer w5: U34D.12@-1670.38,388.58 v1(-1639.57,388.58) ; v3(-236.22,39.37) U50.M17@-216.54,19.69
  Int5 (ST) w5: v1(-1639.57,388.58) -1362.22,388.58 cw(c-1362.22,232.27) -1251.69,342.8 ccw(c-1184.48,410.01) -1184.48,314.96 -602.36,314.96 cw(c-602.36,215.16) -531.79,285.73 -531.26,285.19 ccw(c-460.55,355.91) -460.55,255.91 -236.5,255.91 ; v3(-236.22,39.37) -230.45,45.14 ccw(c-264.06,78.74) -216.54,78.74 -216.54,236.22 ccw(c-236.22,236.22) -236.22,255.91
ADC4.SCLK: R417D.1 U34D.2 U50.M22 | length 1357.4
  Top Layer w5: U34D.2@-1670.38,191.73 v1(-1639.57,191.73) ; v3(-452.76,19.69) U50.M22@-413.39,19.69
  Int5 (ST) w5: v1(-1639.57,191.73) -1536.3,191.73 cw(c-1536.3,72.05) -1451.67,156.68 -1389.11,94.11 ccw(c-1304.48,178.74) -1304.48,59.06 -982.56,59.06 ccw(c-982.56,145.95) -921.12,84.51 cw(c-863.75,27.14) -863.75,108.27 -797.89,108.27 cw(c-797.89,-11.42) -713.26,73.21 -712.74,72.69 ccw(c-656.05,129.39) -656.05,49.21 -564.09,49.21 cw(c-564.09,-5.03) -525.73,33.32 ccw(c-492.8,66.25) -492.8,19.69 v3(-452.76,19.69)
  Bottom Layer w5: R417D.1@-1658.44,191.73 v1(-1639.57,191.73)
ADC4.SI: U34D.4 U50.N22 | length 1332.8
  Top Layer w5: U34D.4@-1670.38,231.1 v1@-1639.53,231.1 ; v3(-452.76,59.06) U50.N22@-413.39,59.06
  Int5 (ST) w5: v1(-1639.57,231.1) -1350.26,231.1 cw(c-1350.26,131.1) -1279.55,201.81 -1249.89,172.15 ccw(c-1095.66,326.38) -1095.66,108.27 -987.32,108.27 ccw(c-987.32,182.2) -935.04,129.92 cw(c-892.27,87.15) -892.27,147.64 -649.69,147.64 cw(c-649.69,47.64) -578.98,118.35 -548.97,88.34 ccw(c-478.26,159.06) -478.26,59.06 v3(-452.76,59.06)
ADC4.SO: U34D.3 U50.M21 | length 1386.1
  Top Layer w5: U34D.3@-1670.38,211.42 v1(-1639.57,211.42) ; v3(-393.7,39.37) U50.M21@-374.02,19.69
  Int5 (ST) w5: v1(-1639.57,211.42) -1536.3,211.42 cw(c-1536.3,72.05) -1437.75,170.6 -1375.19,108.03 ccw(c-1304.48,178.74) -1304.48,78.74 -982.56,78.74 ccw(c-982.56,145.95) -935.04,98.43 cw(c-863.75,27.14) -863.75,127.95 -797.89,127.95 cw(c-797.89,-11.42) -699.34,87.13 -698.82,86.61 ccw(c-656.05,129.39) -656.05,68.9 -564.09,68.9 cw(c-564.09,-5.03) -511.81,47.24 ccw(c-492.8,66.25) -492.8,39.37 v3(-393.7,39.37)
ADC5.CS: R401E.1 U34E.1 U50.J19 | length 1623.8
  Top Layer w5: U34E.1@-1670.38,-277.95 v1(-1639.57,-277.95) ; U50.J19@-295.28,-98.43 v6(-275.59,-78.74)
  Int5 (ST) w5: v1(-1639.57,-277.95) ccw(c-1619.54,-257.92) -1619.54,-286.25 -1547.32,-286.25 cw(c-1547.32,-383.46) -1478.58,-314.72 -1465.88,-327.43 ccw(c-1353.41,-214.96) -1353.41,-374.02 -759.36,-374.02 ccw(c-759.36,-175.59) -619.05,-315.9 -519.49,-216.34 cw(c-472.44,-263.38) -472.44,-196.85 -334.65,-196.85 ccw(c-334.65,-157.48) -295.28,-157.48 -295.28,-98.43 cw(c-275.59,-98.43) v6(-275.59,-78.74)
  Bottom Layer w5: v1(-1639.57,-277.95) R401E.1@-1620.69,-277.95
ADC5.D0: U34E.10 U50.K22 | length 1333.1
  Top Layer w5: U34E.10@-1670.38,-100.79 v1@-1639.5,-100.79 ; v3(-452.76,-59.06) U50.K22@-413.39,-59.06
  Int5 (ST) w5: v1(-1639.57,-100.79) -1626.38,-87.6 cw(c-1561.25,-152.72) -1561.25,-60.62 -1404.22,-60.62 ccw(c-1404.22,12.74) -1352.34,-39.13 -1349.97,-36.76 cw(c-1308.74,-77.99) -1308.74,-19.69 -1178.09,-19.69 cw(c-1178.09,-139.37) -1093.46,-54.74 -1061.07,-87.13 ccw(c-962.52,11.42) -962.52,-127.95 -784.02,-127.95 ccw(c-784.02,-13.22) -702.9,-94.35 cw(c-665.21,-132.03) -665.21,-78.74 -563.61,-78.74 ccw(c-563.61,-44.66) -539.51,-68.76 cw(c-516.09,-92.18) -516.09,-59.06 v3(-452.76,-59.06)
ADC5.D1: U34E.9 U50.K21 | length 1380.6
  Top Layer w5: U34E.9@-1670.38,-120.47 v1(-1639.57,-120.47) ; v3(-393.7,-78.74) U50.K21@-374.02,-59.06
  Int5 (ST) w5: v1(-1639.57,-120.47) -1626.38,-107.28 cw(c-1561.25,-172.41) -1561.25,-80.3 -1404.22,-80.3 ccw(c-1404.22,12.74) -1338.42,-53.05 -1336.05,-50.68 cw(c-1308.74,-77.99) -1308.74,-39.37 -1178.09,-39.37 cw(c-1178.09,-139.37) -1107.38,-68.66 -1074.98,-101.05 ccw(c-962.52,11.42) -962.52,-147.64 -784.02,-147.64 ccw(c-784.02,-13.22) -688.98,-108.27 cw(c-665.21,-132.03) -665.21,-98.43 -563.61,-98.43 ccw(c-563.61,-44.66) -525.59,-82.68 cw(c-516.09,-92.18) -516.09,-78.74 v3(-393.7,-78.74)
ADC5.D2: U34E.8 U50.J22 | length 1375.9
  Top Layer w5: U34E.8@-1670.38,-140.16 v1(-1639.57,-140.16) ; v6(-452.76,-98.43) U50.J22@-413.39,-98.43
  Int5 (ST) w5: v1(-1639.57,-140.16) cw(c-1609.01,-170.72) -1609.01,-127.5 -1549.75,-127.5 cw(c-1549.75,-247.18) -1465.12,-162.55 -1377.81,-249.86 ccw(c-1315.69,-187.74) -1315.69,-275.59 -759.36,-275.59 ccw(c-759.36,-175.59) -688.65,-246.3 -581.59,-139.25 cw(c-483.04,-237.8) -483.04,-98.43 v6(-452.76,-98.43)
ADC5.D3: U34E.7 U50.J21 | length 1423.4
  Top Layer w5: U34E.7@-1670.38,-159.84 v1(-1639.57,-159.84) ; v6(-393.7,-118.11) U50.J21@-374.02,-98.43
  Int5 (ST) w5: v1(-1639.57,-159.84) cw(c-1609.01,-190.4) -1609.01,-147.18 -1549.75,-147.18 cw(c-1549.75,-247.18) -1479.04,-176.47 -1391.73,-263.78 ccw(c-1315.69,-187.74) -1315.69,-295.28 -759.36,-295.28 ccw(c-759.36,-175.59) -674.73,-260.22 -567.67,-153.17 cw(c-483.04,-237.8) -483.04,-118.11 v6(-393.7,-118.11)
ADC5.DCLK: U34E.11 U50.L20 | length 1470.7
  Top Layer w5: U34E.11@-1670.38,-81.1 v1(-1639.57,-81.1) ; U50.L20@-334.65,-19.68 v6(-314.96,-39.37)
  Int5 (ST) w5: v1(-1639.57,-81.1) -1626.38,-67.91 cw(c-1561.25,-133.04) -1561.25,-40.93 -1404.22,-40.93 ccw(c-1404.22,12.74) -1366.26,-25.21 -1363.89,-22.84 cw(c-1308.74,-77.99) -1308.74,0 -1178.09,0 cw(c-1178.09,-139.37) -1079.54,-40.82 -1047.15,-73.21 ccw(c-962.52,11.42) -962.52,-108.27 -784.02,-108.27 ccw(c-784.02,-13.22) -716.82,-80.43 cw(c-665.21,-132.03) -665.21,-59.06 -563.61,-59.06 ccw(c-563.61,-44.66) -553.43,-54.84 cw(c-516.09,-92.18) -516.09,-39.37 -446.99,-39.37 cw(c-446.99,-72.97) -423.23,-49.21 ccw(c-399.47,-25.45) -399.47,-59.06 -354.33,-59.06 ccw(c-354.33,-11.53) -320.73,-45.14 v6(-314.96,-39.37)
ADC5.GPIO7: U34E.18 U50.J16 | length 1759.5
  Top Layer w5: v6(-196.87,-118.42) -196.87,-118.28 -177.17,-98.57 U50.J16@-177.17,-98.43
  Int6 (SB) w5: v1(-1756.1,-7.31) -1756.1,37.65 cw(c-1737.5,37.65) -1737.5,56.25 -1065.49,56.25 cw(c-1065.49,-43.75) -994.78,26.96 -819.94,-147.88 ccw(c-749.23,-77.17) -749.23,-177.17 -275.59,-177.17 ccw(c-275.59,-157.48) -255.91,-157.48 cw(c-236.22,-157.48) -236.22,-137.8 ccw(c-236.22,-114.03) -219.42,-130.84 -214.17,-125.58 cw(c-196.87,-142.88) v6(-196.87,-118.42)
ADC5.ODR: U34E.12 U50.L21 | length 1432.7
  Top Layer w5: U34E.12@-1670.38,-61.42 v1(-1639.57,-61.42) ; U50.L21@-374.02,-19.68 v6(-354.33,-39.37)
  Int5 (ST) w5: v1(-1639.57,-61.42) -1626.38,-48.23 cw(c-1561.25,-113.35) -1561.25,-21.25 -1407.57,-21.25 ccw(c-1407.57,20.83) -1377.83,-8.94 -1380.18,-11.29 ; -1377.81,-8.92 cw(c-1308.74,-77.99) -1308.74,19.69 -1178.09,19.69 cw(c-1178.09,-139.37) -1065.62,-26.9 -1033.23,-59.29 ccw(c-962.52,11.42) -962.52,-88.58 ; -964.57,-88.58 -962.52,-88.58 ; v6(-354.33,-39.37) -360.1,-33.6 ccw(c-393.7,-67.21) -393.7,-19.68 -781.41,-19.68 ccw(c-781.41,-119.68) -852.12,-48.97 -862.44,-59.29 cw(c-933.15,11.42) -933.15,-88.58 -962.52,-88.58
ADC5.SCLK: R417E.1 U34E.2 U50.J20 | length 1575.7
  Top Layer w5: U34E.2@-1670.38,-258.27 v1(-1639.57,-258.27) ; U50.J20@-334.65,-98.43 v6(-314.96,-78.74)
  Int5 (ST) w5: v1(-1639.57,-258.27) ccw(c-1619.54,-238.24) -1619.54,-266.56 -1540.32,-266.56 cw(c-1540.32,-366.56) -1469.61,-295.85 -1451.96,-313.51 ccw(c-1353.41,-214.96) -1353.41,-354.33 -935.04,-354.33 -759.36,-354.33 ccw(c-759.36,-175.59) -632.97,-301.98 -534.8,-203.81 cw(c-470.47,-268.14) -470.47,-177.17 ; -472.44,-177.17 -470.47,-177.17 ; v6(-314.96,-78.74) ccw(c-314.96,-98.43) -334.65,-98.43 -334.65,-157.48 cw(c-354.33,-157.48) -354.33,-177.17 -470.47,-177.17
  Bottom Layer w5: R417E.1@-1658.44,-258.27 v1(-1639.57,-258.27)
ADC5.SI: U34E.4 U50.H22 | length 1349.2
  Top Layer w5: U34E.4@-1670.38,-218.9 v1@-1639.53,-218.9 ; v6(-452.76,-137.8) U50.H22@-413.39,-137.8
  Int5 (ST) w5: v1(-1639.57,-218.9) ccw(c-1619.54,-198.87) -1619.54,-227.19 -1532.17,-227.19 cw(c-1532.17,-346.88) -1447.54,-262.25 -1424.12,-285.67 ccw(c-1353.41,-214.96) -1353.41,-314.96 -935.04,-314.96 -759.36,-314.96 ccw(c-759.36,-175.59) -660.81,-274.14 -553.75,-167.08 cw(c-483.04,-237.8) -483.04,-137.8 v6(-452.76,-137.8)
ADC5.SO: U34E.3 U50.H20 | length 1433.2
  Top Layer w5: U34E.3@-1670.38,-238.58 v1(-1639.57,-238.58) ; v6(-433.07,-157.48) -374.02,-157.48 ccw(c-374.02,-109.96) -340.42,-143.57 U50.H20@-334.65,-137.8
  Int5 (ST) w5: v1(-1639.57,-238.58) ccw(c-1619.54,-218.55) -1619.54,-246.88 -1532.17,-246.88 cw(c-1532.17,-346.88) -1461.46,-276.17 -1438.04,-299.59 ccw(c-1353.41,-214.96) -1353.41,-334.65 -935.04,-334.65 -759.36,-334.65 ccw(c-759.36,-175.59) -646.89,-288.06 -545.6,-186.77 cw(c-474.89,-257.48) -474.89,-157.48 v6(-433.07,-157.48)
ADC6.CS: R401F.1 U34F.1 U50.B21 | length 1547.7
  Top Layer w5: U34F.1@-1670.38,-727.95 v1(-1639.57,-727.95) ; v6(-393.7,-393.7) U50.B21@-374.02,-374.02
  Int5 (ST) w5: v1(-1639.57,-727.95) -1081.91,-727.95 ccw(c-1081.91,-568.9) -969.45,-681.37 ; -967.96,-679.88 -969.45,-681.37 ; v6(-393.7,-393.7) -387.93,-399.47 cw(c-421.53,-433.07) -374.02,-433.07 -374.02,-479.71 cw(c-504.54,-479.71) -504.54,-610.24 -840.59,-610.24 ccw(c-840.59,-749.61) -939.14,-651.06 -969.45,-681.37
  Bottom Layer w5: v1(-1639.57,-727.95) R401F.1@-1620.69,-727.95
ADC6.D0: U34F.10 U50.E21 | length 1391.5
  Top Layer w5: U34F.10@-1670.38,-550.79 v1@-1639.5,-550.79 ; v6(-433.07,-275.59) -413.39,-275.59 ccw(c-413.39,-228.07) U50.E21@-379.79,-261.68 ; U50.E21@-379.78,-261.67 U50.E21@-374.02,-255.91
  Int5 (ST) w5: v1(-1639.57,-550.79) -1135.52,-550.79 ccw(c-1135.52,-411.42) -1036.97,-509.97 -1026.34,-499.34 cw(c-913.87,-611.81) -913.87,-452.76 -778.75,-452.76 ; -775.59,-452.76 -778.75,-452.76 ; v6(-433.07,-275.59) -453.51,-275.59 ccw(c-453.51,-375.59) -524.22,-304.88 -596.69,-377.34 cw(c-778.75,-195.28) -778.75,-452.76
ADC6.D1: U34F.9 U50.D22 | length 1345.8
  Top Layer w5: U34F.9@-1670.38,-570.47 v1(-1639.57,-570.47) ; v6(-452.76,-295.28) U50.D22@-413.39,-295.28
  Int5 (ST) w5: v1(-1639.57,-570.47) -1135.52,-570.47 ccw(c-1135.52,-411.42) -1023.05,-523.89 -1012.42,-513.26 cw(c-913.87,-611.81) -913.87,-472.44 -778.75,-472.44 ; -775.59,-472.44 -778.75,-472.44 ; v6(-452.76,-295.28) ccw(c-452.76,-377.42) -510.84,-319.33 -582.77,-391.26 cw(c-778.75,-195.28) -778.75,-472.44
ADC6.D2: U34F.8 U50.D21 | length 1391.3
  Top Layer w5: U34F.8@-1670.38,-590.16 v1(-1639.57,-590.16) ; v6(-433.07,-314.96) -413.39,-314.96 ccw(c-413.39,-267.44) -379.78,-301.04 U50.D21@-374.02,-295.28
  Int5 (ST) w5: v1(-1639.57,-590.16) -1135.52,-590.16 ccw(c-1135.52,-411.42) -1009.13,-537.81 -998.5,-527.18 cw(c-913.87,-611.81) -913.87,-492.13 -778.75,-492.13 ; -775.59,-492.13 -778.75,-492.13 ; v6(-433.07,-314.96) -452.76,-314.96 ccw(c-452.76,-377.42) -496.91,-333.24 -568.85,-405.18 cw(c-778.75,-195.28) -778.75,-492.13
ADC6.D3: U34F.7 U50.C22 | length 1345.8
  Top Layer w4.2: v6(-452.76,-334.65) U50.C22@-413.39,-334.65
  Top Layer w5: U34F.7@-1670.38,-609.84 v1(-1639.57,-609.84)
  Int5 (ST) w5: v1(-1639.57,-609.84) -1135.52,-609.84 ccw(c-1135.52,-411.42) -995.21,-551.73 -984.58,-541.1 cw(c-913.87,-611.81) -913.87,-511.81 -778.75,-511.81 ; -775.59,-511.81 -778.75,-511.81 ; v6(-452.76,-334.65) ccw(c-452.76,-377.42) -483,-347.17 -554.93,-419.1 cw(c-778.75,-195.28) -778.75,-511.81
ADC6.DCLK: U34F.11 U50.E22 | length 1349.9
  Top Layer w5: U34F.11@-1670.38,-531.1 v1(-1639.57,-531.1) ; v6@-456.69,-255.91 v6(-452.76,-255.91) U50.E22@-413.39,-255.91
  Int5 (ST) w5: v1(-1639.57,-531.1) -1135.52,-531.1 ccw(c-1135.52,-411.42) -1050.89,-496.05 -1040.26,-485.42 cw(c-913.87,-611.81) -913.87,-433.07 -778.75,-433.07 ; -775.59,-433.07 -778.75,-433.07 ; v6(-452.76,-255.91) -453.51,-255.91 ccw(c-453.51,-375.59) -538.14,-290.96 -610.6,-363.42 cw(c-778.75,-195.28) -778.75,-433.07
ADC6.GPIO7: U34F.18 U50.J15 | length 1836.3
  Top Layer w5: v6(-157.5,-118.42) -157.5,-118.28 -137.8,-98.57 U50.J15@-137.8,-98.43
  Int6 (SB) w5: v1(-1756.1,-457.31) -1756.1,-412.35 cw(c-1737.5,-412.35) -1737.5,-393.75 -760.17,-393.75 ccw(c-760.17,-293.75) -689.46,-364.46 -551.14,-226.14 cw(c-480.43,-296.85) -480.43,-196.85 ; -433.07,-196.85 -480.43,-196.85 ; -276.49,-196.85 -480.43,-196.85 ; -275.59,-196.85 ccw(c-275.59,-173.09) -258.79,-189.89 -253.02,-184.13 cw(c-236.22,-200.93) -236.22,-177.17 ccw(c-236.22,-157.48) -216.54,-157.48 cw(c-196.85,-157.48) -196.85,-137.8 ccw(c-196.85,-114.03) -180.05,-130.84 -174.8,-125.58 cw(c-157.5,-142.88) v6(-157.5,-118.42)
ADC6.ODR: U34F.12 U50.F21 | length 1391.4
  Top Layer w5: U34F.12@-1670.38,-511.42 v1(-1639.57,-511.42) ; v3(-433.07,-236.22) -413.39,-236.22 ccw(c-413.39,-188.7) U50.F21@-379.79,-222.31 ; U50.F21@-379.78,-222.3 U50.F21@-374.02,-216.54
  Int5 (ST) w5: v1(-1639.57,-511.42) -1135.52,-511.42 ccw(c-1135.52,-411.42) -1064.81,-482.13 -1054.18,-471.5 cw(c-913.87,-611.81) -913.87,-413.39 -778.75,-413.39 ; -775.59,-413.39 -778.75,-413.39 ; v3(-433.07,-236.22) -453.51,-236.22 ccw(c-453.51,-375.59) -552.06,-277.04 -624.52,-349.5 cw(c-778.75,-195.28) -778.75,-413.39
ADC6.SCLK: R417F.1 U34F.2 U50.A21 | length 1471.3
  Top Layer w5: U34F.2@-1670.38,-708.27 v1(-1639.57,-708.27) ; v6(-393.7,-433.07) U50.A21@-374.02,-413.39
  Int5 (ST) w5: v1(-1639.57,-708.27) -1081.91,-708.27 ccw(c-1081.91,-568.9) -983.37,-667.45 ; -981.88,-665.97 -983.37,-667.45 ; v6(-393.7,-433.07) -393.7,-479.71 cw(c-504.54,-479.71) -504.54,-590.55 -840.59,-590.55 ccw(c-840.59,-749.61) -953.06,-637.14 -983.37,-667.45
  Bottom Layer w5: R417F.1@-1658.44,-708.27 v1(-1639.57,-708.27)
ADC6.SI: U34F.4 U50.B22 | length 1467.7
  Top Layer w5: U34F.4@-1670.38,-668.9 v1@-1639.53,-668.9 ; v6(-433.07,-354.33) U50.B22@-413.39,-374.02
  Int5 (ST) w5: v1(-1639.57,-668.9) -1081.92,-668.9 ccw(c-1081.92,-568.9) -1011.2,-639.61 -980.89,-609.3 cw(c-840.59,-749.61) -840.59,-551.18 -503.54,-551.18 ccw(c-503.54,-480.71) -433.07,-480.71 v6(-433.07,-354.33)
ADC6.SO: U34F.3 U50.C20 | length 1535.4
  Top Layer w5: U34F.3@-1670.38,-688.58 v1(-1639.57,-688.58)
  Top Layer w6: v3(-354.33,-354.33) U50.C20@-334.65,-334.65
  Int5 (ST) w5: v1(-1639.57,-688.58) -1081.92,-688.58 ccw(c-1081.92,-568.9) -997.29,-653.53 -966.97,-623.22 cw(c-840.59,-749.61) -840.59,-570.87 -504.04,-570.87 ccw(c-504.04,-480.21) -413.39,-480.21 -413.39,-393.7 cw(c-393.7,-393.7) -393.7,-374.02 ccw(c-393.7,-326.49) -360.1,-360.1 v3(-354.33,-354.33)
ADC7.CS: R401G.1 U34G.1 U50.B16 | length 2120.9
  Top Layer w5: U34G.1@-1670.38,-1177.95 v1(-1639.57,-1177.95) ; U50.B16@-177.17,-374.02 v6(-157.48,-393.7)
  Int5 (ST) w5: v1(-1639.57,-1177.95) -1302.5,-1177.95 ccw(c-1302.5,-900.79) -1106.52,-1096.77 -934.7,-924.96 cw(c-863.99,-995.67) -863.99,-895.67 -253.94,-895.67 ccw(c-253.94,-799.21) -157.48,-799.21 v6(-157.48,-393.7)
  Bottom Layer w5: v1(-1639.57,-1177.95) R401G.1@-1620.69,-1177.95
ADC7.D0: U34G.10 U50.D20 | length 1799.8
  Top Layer w5: U34G.10@-1670.38,-1000.79 v1@-1639.5,-1000.79 ; U50.D20@-334.65,-295.28 v3(-314.96,-314.96)
  Int5 (ST) w5: v1(-1639.57,-1000.79) -1263.13,-1000.79 ccw(c-1263.13,-861.42) -1164.58,-959.97 -903.2,-698.58 cw(c-832.49,-769.29) -832.49,-669.29 -504.54,-669.29 ccw(c-504.54,-479.71) -314.96,-479.71 -314.96,-446.99 ccw(c-348.56,-446.99) -324.8,-423.23 cw(c-301.04,-399.47) -334.65,-399.55 -334.65,-334.65 cw(c-314.96,-334.65) v3(-314.96,-314.96)
ADC7.D1: U34G.9 U50.A19 | length 1686.2
  Top Layer w5: U34G.9@-1670.38,-1020.47 v1(-1639.57,-1020.47) ; v6(-295.28,-452.76) U50.A19@-295.28,-413.39
  Int5 (ST) w5: v1(-1639.57,-1020.47) -1263.13,-1020.47 ccw(c-1263.13,-861.42) -1150.66,-973.89 -900.81,-724.03 cw(c-816.18,-808.66) -816.18,-688.98 -504.54,-688.98 ccw(c-504.54,-479.71) -295.28,-479.71 v6(-295.28,-452.76)
ADC7.D2: U34G.8 U50.C19 | length 1802.3
  Top Layer w5: U34G.8@-1670.38,-1040.16 v1(-1639.57,-1040.16)
  Top Layer w6: U50.C19@-295.28,-334.65 v3(-275.59,-354.33)
  Int5 (ST) w5: v1(-1639.57,-1040.16) -1263.13,-1040.16 ccw(c-1263.13,-861.42) -1136.75,-987.81 -898.42,-749.48 cw(c-799.87,-848.03) -799.87,-708.66 -504.54,-708.66 ccw(c-504.54,-479.71) -275.59,-479.71 v3(-275.59,-354.33)
ADC7.D3: U34G.7 U50.A18 | length 1746.2
  Top Layer w5: U34G.7@-1670.38,-1059.84 v1(-1639.57,-1059.84) ; v6(-255.91,-452.76) U50.A18@-255.91,-413.39
  Int5 (ST) w5: v1(-1639.57,-1059.84) -1263.13,-1059.84 ccw(c-1263.13,-861.42) -1122.83,-1001.73 -885.35,-764.25 cw(c-798.67,-850.94) -798.67,-728.35 -504.54,-728.35 ccw(c-504.54,-479.71) -255.91,-479.71 v6(-255.91,-452.76)
ADC7.DCLK: U34G.11 U50.A20 | length 1626.9
  Top Layer w5: U34G.11@-1670.38,-981.1 v1(-1639.57,-981.1) ; v6(-334.65,-452.76) U50.A20@-334.65,-413.39
  Int5 (ST) w5: v1(-1639.57,-981.1) -1263.13,-981.1 ccw(c-1263.13,-861.42) -1178.5,-946.05 -911.35,-678.9 cw(c-840.64,-749.61) -840.64,-649.61 -504.54,-649.61 ccw(c-504.54,-479.71) -334.65,-479.71 v6(-334.65,-452.76)
ADC7.GPIO7: U34G.18 U50.G16 | length 1989.7
  Top Layer w5: v6(-196.85,-157.48) U50.G16@-177.17,-177.17
  Int6 (SB) w5: v1(-1756.1,-907.31) -1756.1,-862.35 cw(c-1737.5,-862.35) -1737.5,-843.75 -938.46,-843.75 ccw(c-938.46,-743.75) -867.75,-814.46 -424.41,-371.12 ccw(c-484.19,-316.99) -403.54,-316.99 -403.54,-236.22 cw(c-383.86,-236.22) -383.86,-216.54 -285.43,-216.54 ccw(c-285.43,-121.49) -218.22,-188.7 -203.81,-174.28 ccw(c-220.61,-157.48) v6(-196.85,-157.48)
ADC7.ODR: U34G.12 U50.B20 | length 1643.5
  Top Layer w5: U34G.12@-1670.38,-961.42 v1(-1639.57,-961.42)
  Top Layer w6: v3(-354.33,-393.7) U50.B20@-334.65,-374.02
  Int5 (ST) w5: v1(-1639.57,-961.42) -1263.13,-961.42 ccw(c-1263.13,-861.42) -1192.42,-932.13 -925.27,-664.98 cw(c-840.64,-749.61) -840.64,-629.92 -504.54,-629.92 ccw(c-504.54,-479.71) -354.33,-479.71 v3(-354.33,-393.7)
ADC7.SCLK: R417G.1 U34G.2 U50.A16 | length 2042.4
  Top Layer w5: U34G.2@-1670.38,-1158.27 v1(-1639.57,-1158.27) ; v6(-177.17,-452.76) U50.A16@-177.17,-413.39
  Int5 (ST) w5: v1(-1639.57,-1158.27) -1302.5,-1158.27 ccw(c-1302.5,-900.79) -1120.44,-1082.85 -948.62,-911.04 cw(c-863.99,-995.67) -863.99,-875.98 -253.94,-875.98 ccw(c-253.94,-799.21) -177.17,-799.21 v6(-177.17,-452.76)
  Bottom Layer w5: R417G.1@-1658.44,-1158.27 v1(-1639.57,-1158.27)
ADC7.SI: U34G.4 U50.B18 | length 1841
  Top Layer w5: U34G.4@-1670.38,-1118.9 v1@-1639.53,-1118.9 ; U50.B18@-255.91,-374.02 v6(-236.22,-393.7)
  Int5 (ST) w5: v1(-1639.57,-1118.9) -1302.5,-1118.9 ccw(c-1302.5,-900.79) -1148.28,-1055.01 -871.43,-778.17 cw(c-798.67,-850.94) -798.67,-748.03 -504.54,-748.03 ccw(c-504.54,-479.71) -236.22,-479.71 v6(-236.22,-393.7)
ADC7.SO: U34G.3 U50.B17 | length 2040.2
  Top Layer w5: U34G.3@-1670.38,-1138.58 v1(-1639.57,-1138.58) ; U50.B17@-216.54,-374.02 v6(-196.85,-393.7)
  Int5 (ST) w5: v1(-1639.57,-1138.58) -1302.5,-1138.58 ccw(c-1302.5,-900.79) -1134.36,-1068.93 -962.54,-897.12 cw(c-863.99,-995.67) -863.99,-856.3 -253.94,-856.3 ccw(c-253.94,-799.21) -196.85,-799.21 -196.85,-597.82 v6(-196.85,-393.7)
ADC8.CS: R401H.1 U34H.1 U50.E13 | length 2929
  Top Layer w5: U34H.1@-1670.38,-1627.95 v1@-1639.57,-1627.95 ; U50.E13@-59.05,-255.91 v6(-39.37,-275.59)
  Int5 (ST) w5: v1@-1639.57,-1627.95 -1378.87,-1627.95 ccw(c-1378.87,-1331.1) -1168.96,-1541.01 -828.5,-1200.55 cw(c-757.79,-1271.26) -757.79,-1171.26 -159.06,-1171.26 ccw(c-159.06,-894.09) 118.11,-894.09 118.11,-314.96 ccw(c78.74,-314.96) 78.74,-275.59 v6(-39.37,-275.59)
  Bottom Layer w5: v1(-1643.99,-1627.95) R401H.1@-1620.69,-1627.95
ADC8.D0: U34H.10 U50.A14 | length 2276.7
  Top Layer w5: U34H.10@-1670.38,-1450.79 v1@-1639.5,-1450.79 ; v6(-98.43,-452.76) U50.A14@-98.43,-413.39
  Int5 (ST) w5: v1(-1639.57,-1450.79) -1391.38,-1450.79 ccw(c-1391.38,-1291.73) -1278.91,-1404.2 -907.93,-1033.23 cw(c-837.22,-1103.94) -837.22,-1003.94 -237.8,-1003.94 ccw(c-237.8,-864.57) -98.43,-864.57 v6(-98.43,-452.76)
ADC8.D1: U34H.9 U50.C14 | length 2405.8
  Top Layer w5: U34H.9@-1670.38,-1470.47 v1(-1639.57,-1470.47) ; U50.C14@-98.43,-334.65 v6(-78.74,-354.33)
  Int5 (ST) w5: v1(-1639.57,-1470.47) -1349.62,-1470.47 ccw(c-1349.62,-1291.73) -1223.23,-1418.12 -922.14,-1117.03 cw(c-767.91,-1271.26) -767.91,-1053.15 -237.8,-1053.15 ccw(c-237.8,-894.09) -78.74,-894.09 v6(-78.74,-354.33)
ADC8.D2: U34H.8 U50.A13 | length 2349.8
  Top Layer w5: U34H.8@-1670.38,-1490.16 v1(-1639.57,-1490.16) ; v6(-59.06,-452.76) U50.A13@-59.05,-413.39
  Int5 (ST) w5: v1(-1639.57,-1490.16) -1347.65,-1490.16 ccw(c-1347.65,-1291.73) -1207.34,-1432.04 -906.25,-1130.95 cw(c-765.95,-1271.26) -765.95,-1072.83 -237.8,-1072.83 ccw(c-237.8,-894.09) -59.06,-894.09 v6(-59.06,-452.76)
ADC8.D3: U34H.7 U50.B13 | length 2425.4
  Top Layer w5: U34H.7@-1670.38,-1509.84 v1(-1639.57,-1509.84)
  Int5 (ST) w5: v1(-1639.57,-1509.84) -1347.65,-1509.84 ccw(c-1347.65,-1291.73) -1193.42,-1445.96 -892.33,-1144.87 cw(c-765.95,-1271.26) -765.95,-1092.52 -237.8,-1092.52 ccw(c-237.8,-894.09) -39.37,-894.09 -39.37,-437.15 ccw(c-72.97,-437.15) -49.21,-413.39 cw(c-25.45,-389.62) -59.06,-389.62 v6(-59.06,-374.02)
ADC8.DCLK: U34H.11 U50.B15 | length 2293.3
  Top Layer w5: U34H.11@-1670.38,-1431.1 v1(-1639.57,-1431.1) ; U50.B15@-137.8,-374.02 v6(-118.11,-393.7)
  Int5 (ST) w5: v1(-1639.57,-1431.1) -1391.38,-1431.1 ccw(c-1391.38,-1291.73) -1292.83,-1390.28 -921.85,-1019.31 cw(c-837.22,-1103.94) -837.22,-984.25 -237.8,-984.25 ccw(c-237.8,-864.57) -118.11,-864.57 v6(-118.11,-393.7)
